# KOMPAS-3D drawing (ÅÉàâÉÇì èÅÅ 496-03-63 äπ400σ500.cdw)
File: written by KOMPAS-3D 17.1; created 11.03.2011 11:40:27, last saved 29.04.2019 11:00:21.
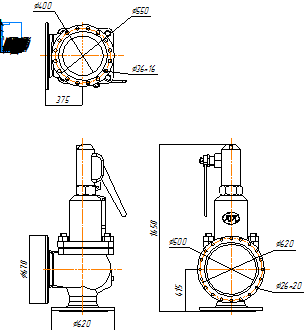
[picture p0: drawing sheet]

Sheet 1: A4, portrait

Title block, sheet 1: name: Прегран Ду400х500; material: Внимание! Данный продукт является объектом авторского права ООО «Торговый Дом АДЛ». / Запрещается изменение, копирование, распространение / (в том числе путем копирования на другие сайты и ресурсы в Интернете) / или любое иное использование информации и объектов без предварительного / согласия правообладателя (ООО «Торговый Дом АДЛ»).; scale: 1:1; sheets: 1; organisation: ООО "Торговый дом АДЛ"; sheet format: A4; stored path: C:\Users\tra\Desktop\2д чертежи\Предохранительные клапаны ПРЕГРАН\ПРЕГРАН 496\ПРЕГРАН КПП 496-03-63\KOMPAS 2D\Прегран Ду400х500.cdw

Views: Спереди 1, Проекционный вид 2, Проекционный вид 3
Dimensions and other numbers on the sheet: 620; 26; 500; 415; 1650; 670; 375; 550; 36; 400; 1:1; 1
